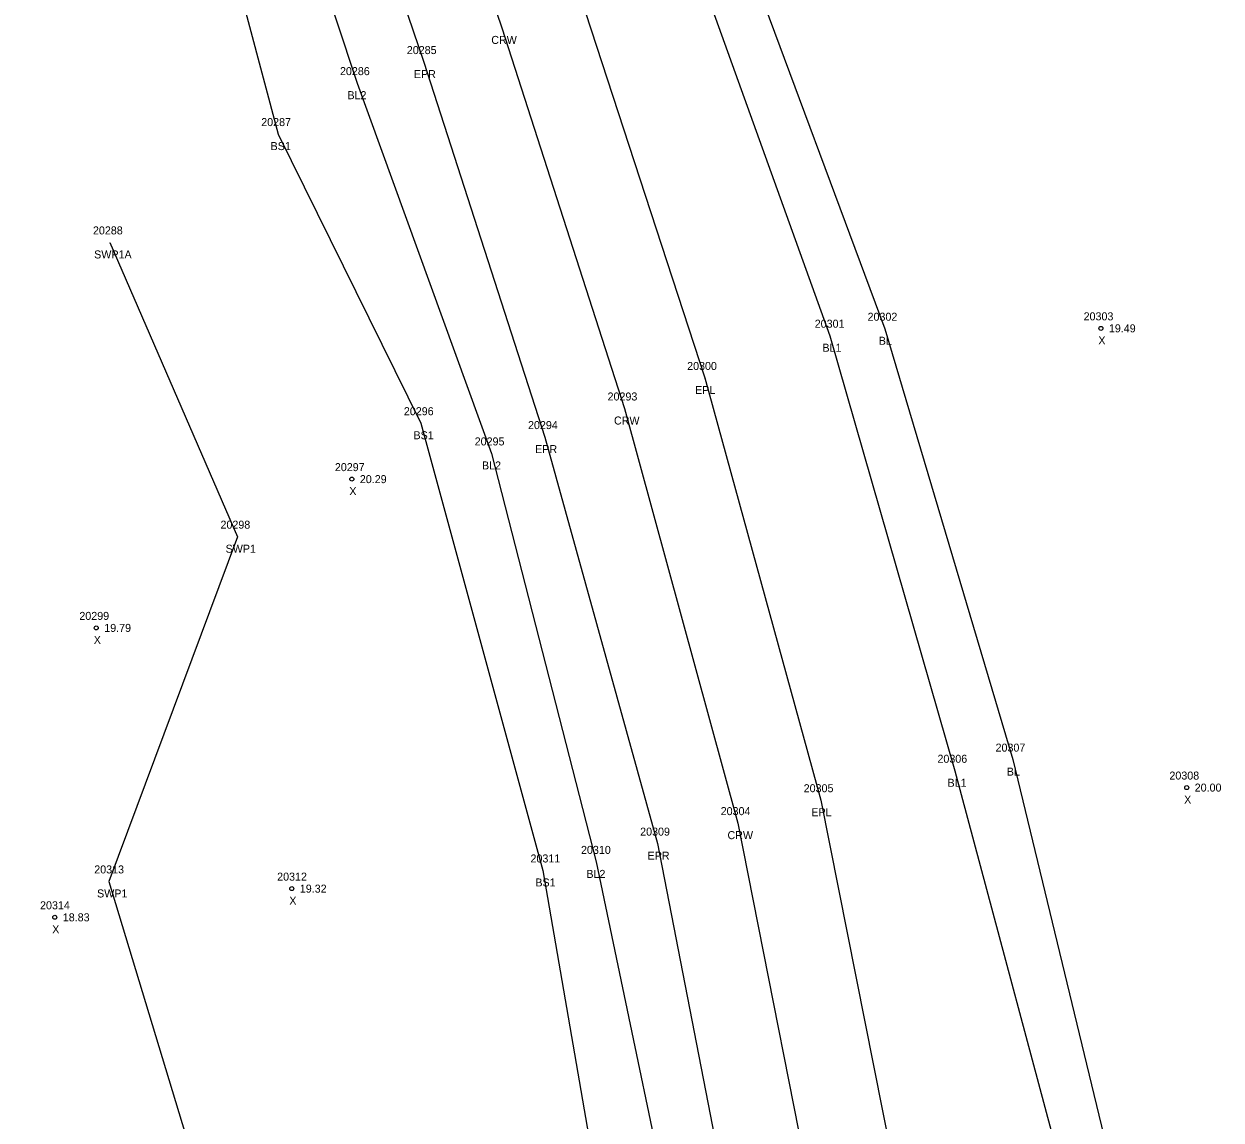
# Model space of a CAD drawing. Extents: x 2432729 to 2433340, y 684958 to 688103.
# Drawn here: x 2433048.8 to 2433198.3, y 686337.6 to 686474.5 of the extents above; entities that cross this region are included whole.
import ezdxf

# ---------------------------------------------------------------- set-up
doc = ezdxf.new("R2010")
doc.units = 0
for name, color, linetype in [('RD_DTM_BkLn1', 7, 'Continuous'), ('RD_DTM_BkLn2', 7, 'Continuous'), ('RD_EX_H2O', 7, 'Continuous'), ('RD_EX_H2O_txCode', 7, 'Continuous'), ('RD_EX_Road', 7, 'Continuous'), ('RD_EX_Road_txCode', 7, 'Continuous'), ('RD_Sketch8', 7, 'Continuous'), ('RD_SMD_Locator', 7, 'Continuous'), ('RD_SMD_Misc', 7, 'Continuous')]:
    doc.layers.add(name, color=color, linetype=linetype)

msp = doc.modelspace()

# ---------------------------------------------------------------- linework, layer by layer
at = {"layer": 'RD_DTM_BkLn1'}
for points in [[(2432926.02, 687213.66), (2432924.35, 687158.94), (2432925.68, 687108.84), (2432939.7, 687000.92), (2432956.93, 686927.39), (2432975, 686866.8), (2433007.19, 686769.33), (2433041.66, 686669.67), (2433075.97, 686569.51), (2433108.49, 686474.01), (2433123.82, 686426.48), (2433137.99, 686374.7), (2433148.76, 686320.1), (2433154.8, 686269.16), (2433155.78, 686212.93), (2433152.37, 686164.52), (2433145.67, 686113.9), (2433140.38, 686078.83)], [(2432898.98, 687049.37), (2432906.9, 687044.55), (2432919.33, 686997.25), (2432938.84, 686920.72), (2432957.15, 686862.46), (2432990.45, 686763.71), (2433024.84, 686664.51), (2433058.68, 686562.8), (2433090.41, 686467.11), (2433107.21, 686420.87), (2433120.26, 686369.86), (2433132.05, 686313.5), (2433136.59, 686267.4), (2433133.92, 686213.17), (2433133.74, 686165.58), (2433125.69, 686115.89), (2433123.08, 686088.41), (2433128.09, 686081.14)], [(2433121.01, 686546.89), (2433138.81, 686483.59), (2433156.33, 686436.44), (2433172.33, 686382.63), (2433186.16, 686325.49), (2433196.85, 686279.41), (2433196.3, 686212.3), (2433190.98, 686162.16), (2433188.39, 686102.75), (2433180.42, 686073.48), (2433172.96, 686068.93), (2433166.53, 686062.55), (2433152.82, 686065.09)], [(2433099.45, 686534.09), (2433116.42, 686534.99), (2433132.92, 686481.52), (2433149.46, 686435.57), (2433165.09, 686381.24), (2433180.28, 686324.44), (2433185.06, 686269.22), (2433188.28, 686211.65), (2433183.39, 686161.81), (2433176.18, 686106.19), (2433174.91, 686080.31), (2433163.5, 686077.21), (2433155.14, 686078.25)]]:
    msp.add_lwpolyline(points, dxfattribs=at)
at = {"layer": 'RD_DTM_BkLn2'}
msp.add_lwpolyline([(2432916.74, 686973.9), (2432925.37, 686926.35), (2432950.18, 686859.06), (2432982.46, 686761.59), (2433017.67, 686659.38), (2433053.8, 686561.16), (2433080.54, 686460.75), (2433098.39, 686424.64), (2433113.62, 686368.79), (2433123.31, 686312.63), (2433128.29, 686266.56), (2433126.49, 686214.47), (2433123.88, 686164.31), (2433114.46, 686111.82), (2433110.48, 686084.68), (2433120.95, 686072.12)], dxfattribs=at)
at = {"layer": 'RD_EX_H2O'}
msp.add_lwpolyline([(2433059.53, 686447.22), (2433075.46, 686410.47), (2433059.4, 686367.42), (2433076.9, 686309.73), (2433110.63, 686264.52), (2433114.63, 686215.04), (2433113.03, 686166.79), (2433114.46, 686111.82), (2433110.48, 686084.68), (2433120.95, 686072.12)], dxfattribs=at)
at = {"layer": 'RD_EX_Road'}
for points in [[(2432915.64, 687215.4), (2432913.86, 687159.12), (2432915.08, 687107.55), (2432919.97, 687053.4), (2432928.7, 686998.89), (2432946.77, 686924.59), (2432964.57, 686864), (2432997.3, 686766.34), (2433031.44, 686666.38), (2433066.06, 686565.78), (2433098.73, 686469.74), (2433113.88, 686422.91), (2433127.93, 686372.14), (2433139.1, 686314.76), (2433144.47, 686268.02), (2433145.44, 686213), (2433142.32, 686164.92), (2433135.44, 686115.75), (2433128.09, 686081.14)], [(2433070.23, 686619.38), (2433072.02, 686607.31), (2433079.53, 686592.62), (2433082.99, 686582.32), (2433082.14, 686577.64), (2433086.96, 686563.7), (2433088.99, 686562.5), (2433099.45, 686534.09), (2433118.26, 686478), (2433133.83, 686430.29), (2433148.35, 686377.56), (2433159.33, 686322.19), (2433165.5, 686270.06), (2433166.43, 686212.82), (2433163.02, 686162.81), (2433156.19, 686111.14), (2433152.88, 686076.43)]]:
    msp.add_lwpolyline(points, dxfattribs=at)
at = {"layer": 'RD_SMD_Locator'}
for centre, radius in [((2433108.49, 686474.01), 0.001), ((2433098.73, 686469.74), 0.001), ((2433090.41, 686467.11), 0.001), ((2433080.54, 686460.75), 0.001), ((2433059.53, 686447.22), 0.001), ((2433183.33, 686436.49), 0.25), ((2433149.46, 686435.57), 0.001), ((2433156.33, 686436.44), 0.001), ((2433133.83, 686430.29), 0.001), ((2433123.82, 686426.48), 0.001), ((2433098.39, 686424.64), 0.001), ((2433113.88, 686422.91), 0.001), ((2433107.21, 686420.87), 0.001), ((2433089.75, 686417.66), 0.25), ((2433075.46, 686410.47), 0.001), ((2433057.82, 686399.08), 0.25), ((2433165.09, 686381.24), 0.001), ((2433172.33, 686382.63), 0.001), ((2433194.05, 686379.14), 0.25), ((2433148.35, 686377.56), 0.001), ((2433137.99, 686374.7), 0.001), ((2433127.93, 686372.14), 0.001), ((2433120.26, 686369.86), 0.001), ((2433113.62, 686368.79), 0.001), ((2433059.4, 686367.42), 0.001), ((2433082.25, 686366.52), 0.25), ((2433052.64, 686362.94), 0.25)]:
    msp.add_circle(centre, radius, dxfattribs=at)

# ---------------------------------------------------------------- texts
at = {"layer": 'RD_EX_H2O_txCode'}
for s, p in [('20288', (2433057.41, 686448.22)), ('SWP1A', (2433057.56, 686445.22)), ('20298', (2433073.34, 686411.47)), ('SWP1', (2433073.98, 686408.47)), ('20313', (2433057.57, 686368.42)), ('SWP1', (2433057.92, 686365.42))]:
    msp.add_text(s, height=1, dxfattribs=at).set_placement(p)
at = {"layer": 'RD_EX_Road_txCode'}
for s, p in [('20285', (2433096.62, 686470.74)), ('EPR', (2433097.5, 686467.74)), ('20300', (2433131.64, 686431.29)), ('EPL', (2433132.63, 686428.29)), ('20294', (2433111.76, 686423.91)), ('EPR', (2433112.65, 686420.91)), ('20305', (2433146.2, 686378.56)), ('EPL', (2433147.15, 686375.56)), ('20309', (2433125.77, 686373.14)), ('EPR', (2433126.7, 686370.14))]:
    msp.add_text(s, height=1, dxfattribs=at).set_placement(p)
at = {"layer": 'RD_Sketch8'}
for s, p in [('20303', (2433181.17, 686437.49)), ('19.49', (2433184.33, 686435.99)), ('X', (2433183.01, 686434.49)), ('20297', (2433087.63, 686418.66)), ('20.29', (2433090.75, 686417.16)), ('X', (2433089.44, 686415.66)), ('20299', (2433055.71, 686400.08)), ('19.79', (2433058.82, 686398.58)), ('X', (2433057.51, 686397.08)), ('20308', (2433191.89, 686380.14)), ('20.00', (2433195.05, 686378.64)), ('X', (2433193.73, 686377.14)), ('20312', (2433080.42, 686367.52)), ('19.32', (2433083.25, 686366.02)), ('20314', (2433050.8, 686363.94)), ('X', (2433081.94, 686364.52)), ('18.83', (2433053.64, 686362.44)), ('X', (2433052.32, 686360.94))]:
    msp.add_text(s, height=1, dxfattribs=at).set_placement(p)
at = {"layer": 'RD_SMD_Misc'}
for s, p in [('CRW', (2433107.17, 686472.01)), ('20286', (2433088.27, 686468.11)), ('BL2', (2433089.2, 686465.11)), ('20287', (2433078.43, 686461.75)), ('BS1', (2433079.6, 686458.75)), ('20302', (2433154.18, 686437.44)), ('20301', (2433147.58, 686436.57)), ('BL', (2433155.58, 686434.44)), ('BL1', (2433148.54, 686433.57)), ('20293', (2433121.7, 686427.48)), ('20296', (2433096.25, 686425.64)), ('CRW', (2433122.5, 686424.48)), ('BS1', (2433097.45, 686422.64)), ('20295', (2433105.1, 686421.87)), ('BL2', (2433106.01, 686418.87)), ('20307', (2433170.17, 686383.63)), ('20306', (2433162.91, 686382.24)), ('BL', (2433171.57, 686380.63)), ('BL1', (2433164.17, 686379.24)), ('20304', (2433135.83, 686375.7)), ('CRW', (2433136.68, 686372.7)), ('20311', (2433112.07, 686369.79)), ('20310', (2433118.38, 686370.86)), ('BS1', (2433112.68, 686366.79)), ('BL2', (2433119.05, 686367.86))]:
    msp.add_text(s, height=1, dxfattribs=at).set_placement(p)

doc.saveas('drawing.dxf')
